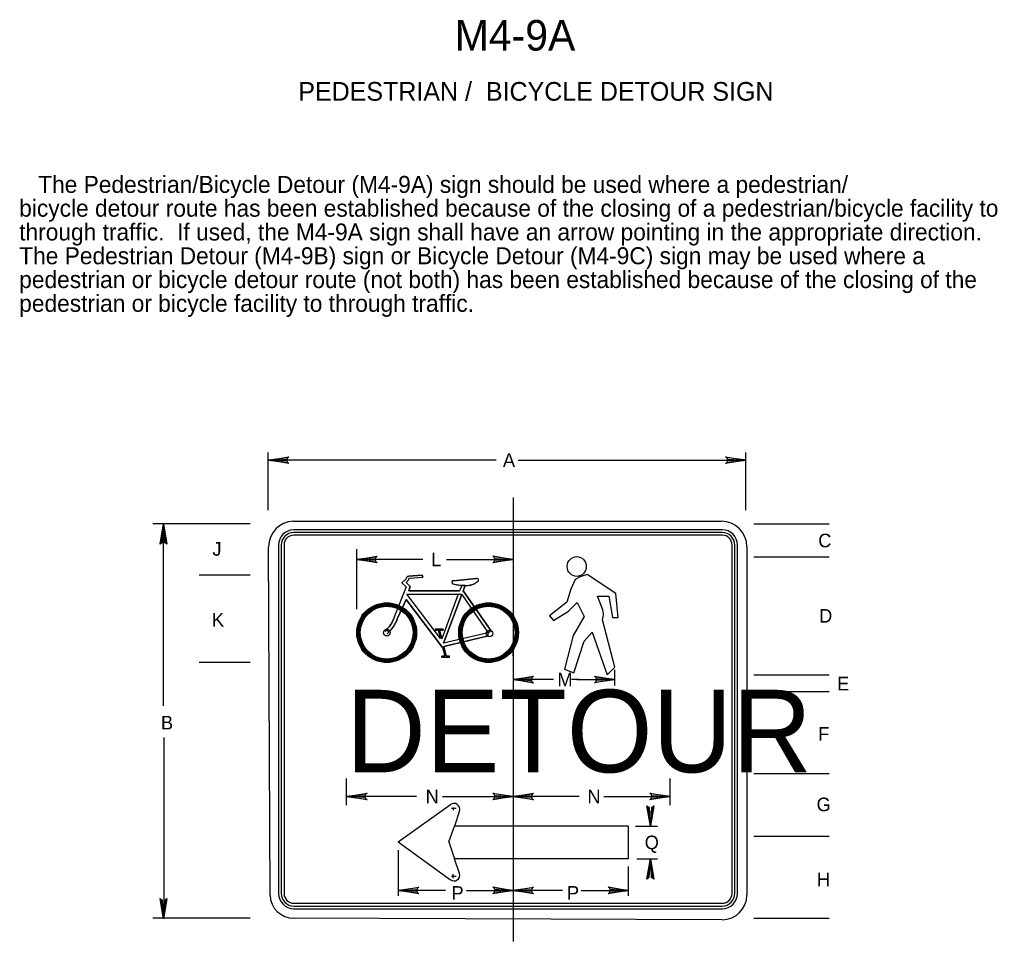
# Model space of a CAD drawing. Extents: x 0.012 to 0.191, y 0.004 to 0.259.
# Drawn here: x 0.0362 to 0.18, y 0.1236 to 0.2592 of the extents above; entities that cross this region are included whole.
import ezdxf

# ---------------------------------------------------------------- set-up
doc = ezdxf.new("R2010")
doc.units = 0
for name, color, linetype in [('1', 7, 'Continuous'), ('2', 7, 'Continuous'), ('3', 7, 'Continuous')]:
    doc.layers.add(name, color=color, linetype=linetype)

# ---------------------------------------------------------------- blocks, each defined once
blk = doc.blocks.new('RARROW')
at = {"layer": '3'}
for p, q in [((-2.156, 0.28500000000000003), (-2.2665, 0.384625)), ((-2.2665, 0.384625), (0, 0)), ((0, 0), (-2.2665, -0.379125)), ((-2.156, 0.28500000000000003), (-2.075625, 0.12075)), ((0, 0), (-2.156, 0.28500000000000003)), ((-2.14975, -0.2705), (0, 0)), ((-2.075625, 0.12075), (0, 0)), ((0, 0), (-2.074, -0.108)), ((-2.2665, -0.379125), (-2.14975, -0.2705)), ((-2.074, -0.108), (-2.14975, -0.2705))]:
    blk.add_line(p, q, dxfattribs=at)

msp = doc.modelspace()

# ---------------------------------------------------------------- linework, layer by layer
at = {"layer": '1'}
msp.add_line((0.10875, 0.18887500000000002), (0.10875, 0.12356034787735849), dxfattribs=at)
at = {"layer": '2'}
for p, q in [((0.076375, 0.185375), (0.139375, 0.185375)), ((0.1395, 0.184125), (0.0765, 0.184125)), ((0.1395, 0.183725), (0.0765, 0.183725)), ((0.1395, 0.183325), (0.0765, 0.183325)), ((0.073, 0.130375), (0.07275, 0.181625)), ((0.07425, 0.181875), (0.07425, 0.130625)), ((0.07465000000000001, 0.181875), (0.07465000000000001, 0.130625)), ((0.07505, 0.181875), (0.07505, 0.130625)), ((0.14095, 0.130625), (0.14095, 0.181875)), ((0.14135, 0.130625), (0.14135, 0.181875)), ((0.14175000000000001, 0.130625), (0.14175000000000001, 0.181875)), ((0.143125, 0.181625), (0.143125, 0.130375)), ((0.0765, 0.129175), (0.1395, 0.129175)), ((0.0765, 0.128775), (0.1395, 0.128775)), ((0.0765, 0.128375), (0.1395, 0.128375)), ((0.1395, 0.12675), (0.0765, 0.127))]:
    msp.add_line(p, q, dxfattribs=at)
for centre, radius, start, end in [((0.07647908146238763, 0.181684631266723), 0.00368802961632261, 90.97102222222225, 180.97102222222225), ((0.07648591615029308, 0.1818871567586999), 0.002235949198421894, 90.31151666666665, 180.31151666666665), ((0.1393750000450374, 0.18162500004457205), 0.0037499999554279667, 0, 90), ((0.13950000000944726, 0.1818750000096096), 0.0022499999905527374, 0, 90), ((0.07648591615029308, 0.1818871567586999), 0.0018359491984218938, 90.31151666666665, 180.31151666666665), ((0.07648591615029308, 0.1818871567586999), 0.0014359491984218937, 90.31151666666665, 180.31151666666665), ((0.13950000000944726, 0.1818750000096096), 0.0018499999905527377, 0, 90), ((0.13950000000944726, 0.1818750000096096), 0.0014499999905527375, 0, 90), ((0.07643750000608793, 0.13043750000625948), 0.0034380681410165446, 181.04162777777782, 271.0416277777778), ((0.07650000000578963, 0.13062500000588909), 0.002250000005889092, 180, 270), ((0.07650000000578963, 0.13062500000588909), 0.001850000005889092, 180, 270), ((0.07650000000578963, 0.13062500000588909), 0.0014500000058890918, 180, 270), ((0.13949999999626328, 0.130625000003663), 0.00225000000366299, 270, 0), ((0.13949999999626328, 0.130625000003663), 0.0018500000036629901, 270, 0), ((0.13949999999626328, 0.130625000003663), 0.00145000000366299, 270, 0), ((0.13949999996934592, 0.13037500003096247), 0.003625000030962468, 270, 0)]:
    msp.add_arc(centre, radius, start, end, dxfattribs=at)
at = {"layer": '3'}
for p, q in [((0.07274167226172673, 0.18700966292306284), (0.07274167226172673, 0.19550966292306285)), ((0.10625, 0.194375), (0.07275, 0.194375)), ((0.1095, 0.194375), (0.14300000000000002, 0.194375)), ((0.14299612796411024, 0.18700966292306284), (0.14299612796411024, 0.19550966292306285)), ((0.07008239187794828, 0.18499713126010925), (0.0557621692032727, 0.18499713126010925)), ((0.05733301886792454, 0.15821797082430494), (0.05733301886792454, 0.185)), ((0.144125, 0.185), (0.15525, 0.185)), ((0.08575991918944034, 0.17246865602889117), (0.08575991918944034, 0.18128389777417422)), ((0.144125, 0.180167), (0.15525, 0.180167)), ((0.09547660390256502, 0.17976620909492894), (0.08575991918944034, 0.17976620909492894)), ((0.09896728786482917, 0.17976620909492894), (0.10875, 0.17976620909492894)), ((0.07008239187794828, 0.17745213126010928), (0.06259512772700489, 0.17745213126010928)), ((0.0929622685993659, 0.17687527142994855), (0.0930897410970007, 0.17713021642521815)), ((0.0930897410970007, 0.17713021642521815), (0.0932172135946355, 0.17725768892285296)), ((0.0932172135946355, 0.17725768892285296), (0.0934084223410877, 0.17732142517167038)), ((0.0932809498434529, 0.17662032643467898), (0.0934721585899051, 0.17700274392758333)), ((0.09334468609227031, 0.1767477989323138), (0.0934721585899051, 0.17700274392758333)), ((0.0934084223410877, 0.17732142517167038), (0.09538424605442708, 0.1774488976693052)), ((0.0934721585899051, 0.17700274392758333), (0.09544798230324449, 0.17713021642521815)), ((0.09538424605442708, 0.1774488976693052), (0.09544798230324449, 0.17713021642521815)), ((0.09997325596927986, 0.17662032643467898), (0.10335127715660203, 0.17693900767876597)), ((0.0930260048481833, 0.17572801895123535), (0.09130512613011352, 0.17139395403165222)), ((0.09238864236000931, 0.17630164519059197), (0.0929622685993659, 0.17687527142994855)), ((0.0930260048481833, 0.17572801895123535), (0.09238864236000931, 0.17630164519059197)), ((0.0930260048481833, 0.17636538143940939), (0.0932809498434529, 0.17662032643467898)), ((0.0935996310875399, 0.1757917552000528), (0.0930260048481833, 0.17636538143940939)), ((0.0935996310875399, 0.1757917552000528), (0.0934084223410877, 0.1751543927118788)), ((0.10118424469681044, 0.1759192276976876), (0.10086556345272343, 0.1751543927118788)), ((0.10169413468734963, 0.1759192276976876), (0.10137545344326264, 0.1751543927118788)), ((0.0930897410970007, 0.1746445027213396), (0.10067435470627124, 0.1746445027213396)), ((0.09806116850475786, 0.16814340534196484), (0.0930897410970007, 0.1746445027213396)), ((0.0934084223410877, 0.1751543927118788), (0.10086556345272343, 0.1751543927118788)), ((0.10067435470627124, 0.1746445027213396), (0.09825237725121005, 0.16807966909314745)), ((0.10118424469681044, 0.1745807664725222), (0.09850732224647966, 0.16744230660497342)), ((0.10118424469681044, 0.1745807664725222), (0.1050721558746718, 0.16897197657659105)), ((0.10137545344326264, 0.1751543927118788), (0.1054545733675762, 0.16929065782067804)), ((0.0930260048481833, 0.17387966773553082), (0.0918150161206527, 0.1712027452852)), ((0.09837984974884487, 0.16680494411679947), (0.0930260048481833, 0.17387966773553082)), ((0.09729633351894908, 0.16948186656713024), (0.09774248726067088, 0.16948186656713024)), ((0.09729633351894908, 0.16948186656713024), (0.09729633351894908, 0.16935439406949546)), ((0.09729633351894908, 0.16935439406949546), (0.09774248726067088, 0.16935439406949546)), ((0.09774248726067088, 0.16948186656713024), (0.09844358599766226, 0.16948186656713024)), ((0.09774248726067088, 0.16935439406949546), (0.09806116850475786, 0.16814340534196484)), ((0.09793369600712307, 0.16935439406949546), (0.09825237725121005, 0.16807966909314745)), ((0.09793369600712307, 0.16935439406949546), (0.09844358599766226, 0.16935439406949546)), ((0.09844358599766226, 0.16948186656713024), (0.09844358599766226, 0.16935439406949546)), ((0.1050721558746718, 0.16897197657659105), (0.09850732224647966, 0.16744230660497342)), ((0.10494468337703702, 0.16846208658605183), (0.09857105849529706, 0.16693241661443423)), ((0.09857105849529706, 0.16693241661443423), (0.09888973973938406, 0.16553021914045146)), ((0.09825237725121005, 0.16553021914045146), (0.09869853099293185, 0.16553021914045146)), ((0.09825237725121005, 0.16540274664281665), (0.09825237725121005, 0.16553021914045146)), ((0.09825237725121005, 0.16540274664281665), (0.09869853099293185, 0.16540274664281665)), ((0.09837984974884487, 0.16680494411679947), (0.09869853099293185, 0.16553021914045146)), ((0.09869853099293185, 0.16540274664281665), (0.09939962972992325, 0.16540274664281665)), ((0.09888973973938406, 0.16553021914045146), (0.09939962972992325, 0.16553021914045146)), ((0.09939962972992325, 0.16540274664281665), (0.09939962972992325, 0.16553021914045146)), ((0.10875, 0.16557287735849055), (0.10875, 0.16657287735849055)), ((0.07008239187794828, 0.16458213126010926), (0.06259512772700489, 0.16458213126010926)), ((0.12370561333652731, 0.16120930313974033), (0.12370561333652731, 0.1635206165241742)), ((0.144125, 0.162767), (0.15525, 0.162767)), ((0.11470698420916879, 0.1620821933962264), (0.10875, 0.1620821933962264)), ((0.11844587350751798, 0.1620821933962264), (0.11733764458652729, 0.1620821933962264)), ((0.11814075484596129, 0.1620821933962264), (0.12370561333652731, 0.1620821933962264)), ((0.144125, 0.1603503), (0.15525, 0.1603503)), ((0.05737460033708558, 0.1535789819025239), (0.05737460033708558, 0.12699713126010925)), ((0.144125, 0.1482703), (0.15525, 0.1482703)), ((0.08425993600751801, 0.14362782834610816), (0.08425993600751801, 0.14752588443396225)), ((0.1318394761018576, 0.14362782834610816), (0.1318394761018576, 0.14752588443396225)), ((0.0945422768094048, 0.1448817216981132), (0.08425993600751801, 0.1448817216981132)), ((0.0983491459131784, 0.1448817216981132), (0.10875, 0.1448817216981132)), ((0.11844587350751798, 0.1448817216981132), (0.10875, 0.1448817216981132)), ((0.12210097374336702, 0.1448817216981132), (0.13119375, 0.1448817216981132)), ((0.09186034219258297, 0.1382025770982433), (0.09952695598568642, 0.14370253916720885)), ((0.10036028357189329, 0.14311920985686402), (0.09969362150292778, 0.14311920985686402)), ((0.1002769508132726, 0.14310866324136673), (0.09969362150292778, 0.14310866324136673)), ((0.09994361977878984, 0.14327532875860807), (0.09994361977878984, 0.14285866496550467)), ((0.09994361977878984, 0.1432025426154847), (0.09994361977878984, 0.14286921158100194)), ((0.10086028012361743, 0.14278587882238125), (0.10011028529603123, 0.14053589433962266)), ((0.09927695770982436, 0.13820257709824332), (0.10011028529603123, 0.14053589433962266)), ((0.12566667, 0.14053589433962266), (0.10011028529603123, 0.14053589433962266)), ((0.12566667, 0.14053589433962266), (0.12566667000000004, 0.13570259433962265)), ((0.12675996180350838, 0.14053589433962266), (0.12999769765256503, 0.14053589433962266)), ((0.09186034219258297, 0.1382025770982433), (0.09952695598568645, 0.1326192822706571)), ((0.09927695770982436, 0.13820257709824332), (0.10011028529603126, 0.13570259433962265)), ((0.144125, 0.1390703), (0.15525, 0.1390703)), ((0.09186735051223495, 0.13025319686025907), (0.09186735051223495, 0.13700533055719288)), ((0.10086028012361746, 0.1335359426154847), (0.10011028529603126, 0.13570259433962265)), ((0.12566667, 0.13570259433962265), (0.10011028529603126, 0.13570259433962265)), ((0.12696232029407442, 0.13570259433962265), (0.12999769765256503, 0.13570259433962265)), ((0.12572445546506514, 0.13025319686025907), (0.12572445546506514, 0.1345643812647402)), ((0.10036028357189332, 0.13311927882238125), (0.09969362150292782, 0.13311927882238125)), ((0.10027695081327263, 0.13310873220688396), (0.09969362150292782, 0.13310873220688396)), ((0.09994361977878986, 0.13303594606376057), (0.09994361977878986, 0.13345260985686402)), ((0.09994361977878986, 0.1328587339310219), (0.09994361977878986, 0.13335873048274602)), ((0.0988234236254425, 0.13107075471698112), (0.09186735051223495, 0.13107075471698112)), ((0.1018967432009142, 0.13107075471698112), (0.10875, 0.13107075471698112)), ((0.11601124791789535, 0.13107075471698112), (0.10875, 0.13107075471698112)), ((0.11876838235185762, 0.13107075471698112), (0.12572445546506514, 0.13107075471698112)), ((0.07008239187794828, 0.12699713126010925), (0.0557621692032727, 0.12699713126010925)), ((0.144125, 0.1269903), (0.15525, 0.1269903))]:
    msp.add_line(p, q, dxfattribs=at)
for points in [[(0.1054545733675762, 0.16929065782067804), (0.10137545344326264, 0.1751543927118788), (0.10169413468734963, 0.1759192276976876), (0.10118424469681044, 0.1759192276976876), (0.10086556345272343, 0.1751543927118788), (0.0934084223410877, 0.1751543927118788), (0.0935996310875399, 0.1757917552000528), (0.0930260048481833, 0.17636538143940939), (0.0932809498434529, 0.17662032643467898), (0.0934721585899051, 0.17700274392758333), (0.09544798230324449, 0.17713021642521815), (0.09538424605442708, 0.1774488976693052), (0.0934084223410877, 0.17732142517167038), (0.0932172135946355, 0.17725768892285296), (0.0930897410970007, 0.17713021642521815), (0.0929622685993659, 0.17687527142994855), (0.09238864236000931, 0.17630164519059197), (0.0930260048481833, 0.17572801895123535), (0.09130512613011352, 0.17139395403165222), (0.09111391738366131, 0.1708203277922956), (0.09092270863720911, 0.17043791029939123), (0.09054029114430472, 0.16986428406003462), (0.09009413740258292, 0.16935439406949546), (0.09054029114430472, 0.16909944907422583), (0.0907314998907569, 0.16935439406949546), (0.0911776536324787, 0.16986428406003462), (0.0915600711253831, 0.17056538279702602), (0.0918150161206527, 0.1712027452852), (0.0930260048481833, 0.17387966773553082), (0.09837984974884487, 0.16680494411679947), (0.09869853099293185, 0.16553021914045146), (0.09825237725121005, 0.16553021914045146), (0.09825237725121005, 0.16540274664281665), (0.09939962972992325, 0.16540274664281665), (0.09939962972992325, 0.16553021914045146), (0.09888973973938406, 0.16553021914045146), (0.09857105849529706, 0.16693241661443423), (0.1050721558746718, 0.16852582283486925), (0.1050721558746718, 0.16897197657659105), (0.09850732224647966, 0.16744230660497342), (0.10118424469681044, 0.1745807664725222), (0.10067435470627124, 0.1746445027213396), (0.09825237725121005, 0.16807966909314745), (0.09793369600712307, 0.16935439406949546), (0.09844358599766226, 0.16935439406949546), (0.09844358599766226, 0.16948186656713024), (0.09729633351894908, 0.16948186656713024), (0.09729633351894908, 0.16935439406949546), (0.09774248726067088, 0.16935439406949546), (0.09806116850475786, 0.16814340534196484), (0.0930897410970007, 0.1746445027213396), (0.10118424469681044, 0.1745807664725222), (0.1050721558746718, 0.16897197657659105)], [(0.10335127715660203, 0.17693900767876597), (0.09997325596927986, 0.17662032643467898), (0.09990951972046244, 0.17662032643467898), (0.09978204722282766, 0.17655659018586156), (0.09971831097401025, 0.17642911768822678), (0.09978204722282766, 0.17623790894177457), (0.09990951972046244, 0.17617417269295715), (0.10041940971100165, 0.1760467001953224), (0.10124798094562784, 0.1759192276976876), (0.10207655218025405, 0.1759192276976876), (0.10245896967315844, 0.17598296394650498), (0.10265017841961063, 0.1760467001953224), (0.10290512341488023, 0.17611043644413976), (0.10322380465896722, 0.17630164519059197), (0.10354248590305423, 0.17649285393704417), (0.10360622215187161, 0.17655659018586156), (0.10366995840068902, 0.17662032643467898), (0.10366995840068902, 0.1767477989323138), (0.10360622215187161, 0.17687527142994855), (0.10347874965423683, 0.17693900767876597)], [(0.11409938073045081, 0.17144693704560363), (0.1146779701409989, 0.17077933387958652), (0.1169033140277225, 0.17215904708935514), (0.11814950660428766, 0.17344974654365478), (0.11917316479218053, 0.1713579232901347), (0.11757091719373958, 0.168553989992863), (0.11628021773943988, 0.1636137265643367), (0.11765993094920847, 0.16307964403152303), (0.11921767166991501, 0.1677528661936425), (0.12037485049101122, 0.16904356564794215), (0.12255568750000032, 0.16276809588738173), (0.12371286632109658, 0.16392527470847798), (0.12188808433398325, 0.17086834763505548), (0.12197709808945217, 0.17131341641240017), (0.12202160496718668, 0.1716249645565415), (0.12202160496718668, 0.17184749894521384), (0.12197709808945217, 0.17207003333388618), (0.12193259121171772, 0.17233707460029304), (0.12117597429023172, 0.17433988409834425), (0.12282272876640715, 0.17433988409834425), (0.1233568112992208, 0.17122440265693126), (0.12420244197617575, 0.17122440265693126), (0.12384638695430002, 0.1747404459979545), (0.11961823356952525, 0.17754437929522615), (0.11859457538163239, 0.17718832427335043), (0.11788246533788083, 0.1768322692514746), (0.11721486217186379, 0.17540804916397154), (0.11663627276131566, 0.1734942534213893)]]:
    msp.add_lwpolyline(points, close=True, dxfattribs=at)
for centre, radius in [((0.0901577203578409, 0.1689904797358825), 0.004397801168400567), ((0.0901577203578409, 0.1689904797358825), 0.004346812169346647), ((0.0901577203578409, 0.1689904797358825), 0.004295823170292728), ((0.0901577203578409, 0.1689904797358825), 0.004244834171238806), ((0.0901577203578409, 0.1689904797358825), 0.004193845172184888), ((0.0901577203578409, 0.1689904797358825), 0.004142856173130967), ((0.0901577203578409, 0.1689904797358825), 0.004091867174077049), ((0.0901577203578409, 0.1689904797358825), 0.004040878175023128), ((0.0901577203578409, 0.1689904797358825), 0.00398988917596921), ((0.0901577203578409, 0.1689904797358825), 0.003938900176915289), ((0.0901577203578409, 0.1689904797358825), 0.00388791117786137), ((0.10513573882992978, 0.1689904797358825), 0.004397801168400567), ((0.10513573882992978, 0.1689904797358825), 0.004346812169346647), ((0.10513573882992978, 0.1689904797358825), 0.004295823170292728), ((0.10513573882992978, 0.1689904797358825), 0.004244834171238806), ((0.10513573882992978, 0.1689904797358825), 0.004193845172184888), ((0.10513573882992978, 0.1689904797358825), 0.004142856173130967), ((0.10513573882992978, 0.1689904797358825), 0.004091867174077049), ((0.10513573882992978, 0.1689904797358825), 0.004040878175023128), ((0.10513573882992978, 0.1689904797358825), 0.00398988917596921), ((0.10513573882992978, 0.1689904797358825), 0.003938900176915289), ((0.10513573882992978, 0.1689904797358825), 0.00388791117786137), ((0.0901577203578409, 0.1689904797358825), 0.00048540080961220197), ((0.1052632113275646, 0.16886300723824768), 0.00048540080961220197)]:
    msp.add_circle(centre, radius, dxfattribs=at)
for centre, radius, start, end in [((0.09994123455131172, 0.1764157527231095), 0.00022534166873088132, 81.86989722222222, 261.8698972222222), ((0.1018851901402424, 0.18368965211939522), 0.00775296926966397, 255.23545833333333, 270.9420861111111), ((0.10178379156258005, 0.17882034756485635), 0.002891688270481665, 274.53958888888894, 309.0632305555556), ((0.08617849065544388, 0.17319425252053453), 0.005461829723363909, 312.61111111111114, 340.70747500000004), ((0.08617849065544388, 0.17319425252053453), 0.0059717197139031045, 312.61111111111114, 340.70747500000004), ((0.10004468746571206, 0.1430170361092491), 0.0008506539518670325, 343.4926194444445, 127.49033611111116), ((0.10004659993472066, 0.13331141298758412), 0.0008506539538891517, 232.50966388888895, 16.507380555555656)]:
    msp.add_arc(centre, radius, start, end, dxfattribs=at)
msp.add_ellipse((0.1181016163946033, 0.17872194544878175), major_axis=(8.937169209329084e-20, 0.0014595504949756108), ratio=0.9570312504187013, dxfattribs=at)

# ---------------------------------------------------------------- block references
at = {"layer": '3', "xscale": 0.0013236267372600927, "yscale": 0.001309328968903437}
for p, rotation in [((0.07275, 0.194375), 180), ((0.05733301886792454, 0.185), 90), ((0.08575549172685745, 0.17976620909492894), 180), ((0.10875, 0.1620821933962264), 180), ((0.08425993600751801, 0.1448817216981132), 180), ((0.10875, 0.1448817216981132), 180), ((0.12893057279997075, 0.14053589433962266), -90), ((0.12893057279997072, 0.13570259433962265), 90), ((0.09186735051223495, 0.13107075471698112), 180), ((0.10875, 0.13107075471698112), 180), ((0.05733301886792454, 0.12687500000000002), -90)]:
    msp.add_blockref('RARROW', p, dxfattribs=dict(at, rotation=rotation))
for p in [(0.14300000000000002, 0.194375), (0.10875, 0.17976620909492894), (0.12370561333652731, 0.1620821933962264), (0.10875, 0.1448817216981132), (0.1318394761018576, 0.1448817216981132), (0.10875, 0.13107075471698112), (0.12572445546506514, 0.13107075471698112)]:
    msp.add_blockref('RARROW', p, dxfattribs=at)

# ---------------------------------------------------------------- texts
at = {"layer": '1'}
for s, height, p in [('M4-9A', 0.0045000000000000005, (0.1001684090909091, 0.254625)), ('PEDESTRIAN /  BICYCLE DETOUR SIGN', 0.00275025, (0.07715025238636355, 0.24725)), ('DETOUR', 0.01213425, (0.08418428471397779, 0.14844787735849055))]:
    msp.add_text(s, height=height, dxfattribs=at).set_placement(p)
at = {"layer": '2'}
for s, p in [('   The Pedestrian/Bicycle Detour (M4-9A) sign should be used where a pedestrian/', (0.03610613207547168, 0.23368853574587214)), ('bicycle detour route has been established because of the closing of a pedestrian/bicycle facility to ', (0.03610613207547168, 0.23018878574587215)), ('through traffic.  If used, the M4-9A sign shall have an arrow pointing in the appropriate direction.  ', (0.03610613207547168, 0.22668903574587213)), ('The Pedestrian Detour (M4-9B) sign or Bicycle Detour (M4-9C) sign may be used where a ', (0.03610613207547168, 0.22318928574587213)), ('pedestrian or bicycle detour route (not both) has been established because of the closing of the ', (0.03610613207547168, 0.21968953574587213)), ('pedestrian or bicycle facility to through traffic.', (0.03610613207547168, 0.21618978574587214))]:
    msp.add_text(s, height=0.0024997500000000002, dxfattribs=at).set_placement(p)
at = {"layer": '3'}
for s, height, p in [('A', 0.00200025, (0.10725, 0.193375)), ('C', 0.00200025, (0.153625, 0.1815477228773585)), ('J', 0.00200025, (0.06452403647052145, 0.18030906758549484)), ('L', 0.002, (0.09668794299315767, 0.17876620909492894)), ('K', 0.00200025, (0.06445298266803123, 0.1698876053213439)), ('D', 0.00200025, (0.15375, 0.170466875)), ('M', 0.002, (0.11526207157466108, 0.1610821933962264)), ('E', 0.00200025, (0.15640124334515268, 0.16049156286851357)), ('B', 0.00200025, (0.05695801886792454, 0.15475)), ('F', 0.00200025, (0.15362303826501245, 0.15310547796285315)), ('N', 0.002, (0.0958830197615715, 0.1438817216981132)), ('N', 0.002, (0.11967278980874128, 0.1438817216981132)), ('G', 0.00200025, (0.153375, 0.1427197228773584)), ('Q', 0.002, (0.12809807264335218, 0.13712800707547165)), ('H', 0.00200025, (0.1534299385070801, 0.13169118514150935)), ('P', 0.002, (0.09968672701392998, 0.12969427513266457)), ('P', 0.002, (0.11666118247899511, 0.12970692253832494))]:
    msp.add_text(s, height=height, dxfattribs=at).set_placement(p)

doc.saveas('drawing.dxf')
